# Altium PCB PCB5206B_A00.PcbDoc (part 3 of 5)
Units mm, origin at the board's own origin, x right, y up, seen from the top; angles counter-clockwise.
Board outline 115 x 60 mm, 6 copper layers (Top Layer, GND Layer 2, Signal Layer 3, Signal Layer 4, VCC Layer 5, Bottom Layer), stack 1.555 mm thick; 384 components, 267 nets, 1313 pads, 834 vias.
Unrouted connection lines stored in the file: 10.
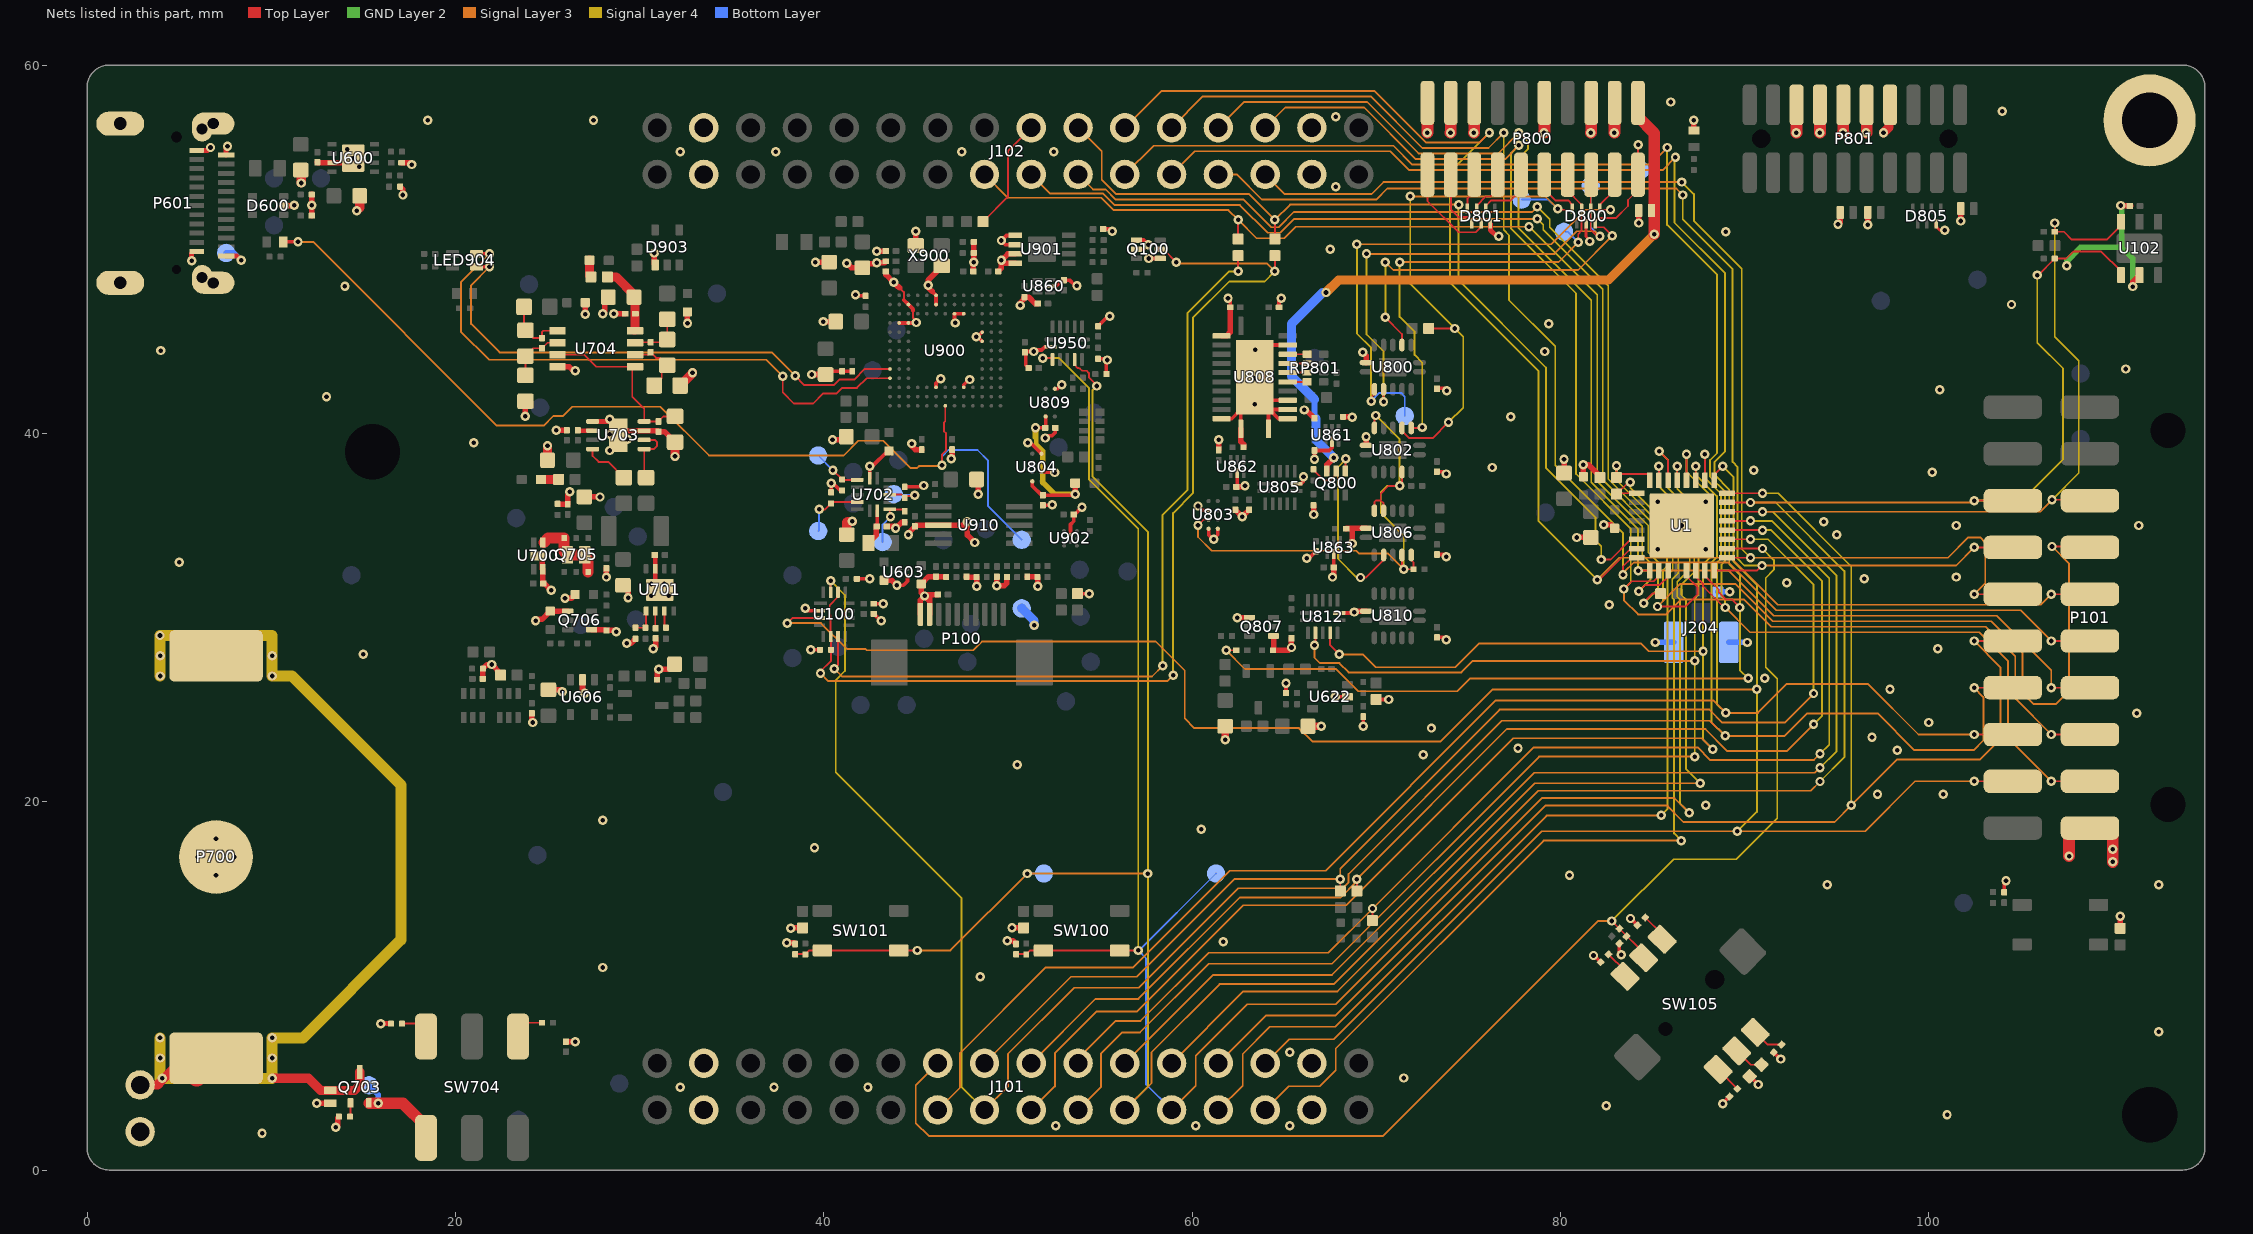
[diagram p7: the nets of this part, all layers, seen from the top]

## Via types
v1: diameter 0.508, hole 0.25, Top Layer to Bottom Layer, tented both sides, 834 vias

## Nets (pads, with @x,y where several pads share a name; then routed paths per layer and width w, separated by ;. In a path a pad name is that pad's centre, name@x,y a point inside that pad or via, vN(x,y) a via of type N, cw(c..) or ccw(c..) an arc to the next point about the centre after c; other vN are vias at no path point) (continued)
DEBUG_TRACECLK: D801.2 P800.12 | length 3.2
  Top Layer w0.1: D801.2@75.95,52.215 75.95,52.35 76.25,52.65 77.3,52.65 77.865,53.215 P800.12@77.865,54.05
DEBUG_TRACED0: D801.3 P800.14 | length 2.5
  Top Layer w0.1: D801.3@75.45,52.215 75.45,52.375 75.95,52.875 76.225,52.875 76.595,53.245 P800.14@76.595,54.05
DEBUG_TRACED1: D801.4 P800.16 | length 2
  Top Layer w0.1: D801.4@74.95,52.215 74.95,52.75 75.325,53.125 P800.16@75.325,54.05
DEBUG_TRACED2: D801.5 P800.18 | length 3.4
  Top Layer w0.1: P800.18@74.055,54.05 74.055,52.17 74.475,51.75 75,51.75 75.2,51.55 D801.5@75.2,51.385
DEBUG_TRACED3: D801.6 P800.20 | length 5.3
  Top Layer w0.1: P800.20@72.785,54.05 72.785,52.615 74.475,50.925 75.4,50.925 75.7,51.225 D801.6@75.7,51.385
DH_#RESET: D800.4 P800.10 R816.1 TPJ811.1 U802.3 | length 32.5
  Top Layer w0.1: U802.3@71.4,40.3 71.4,40.15 71.8,39.75 73.075,39.75 v1(73.925,40.6) ; R816.1@72.85,45.7 v1@74.175,45.7 ; P800.10@79.135,54.05 79.135,53.24 79.725,52.65 80.425,52.65 80.65,52.425 D800.4@80.65,52.215 80.585,52.15 79.85,52.15 v1(79.85,52.193)
  Signal Layer 3 w0.1: v1(71.85,52.875) 79.168,52.875 v1(79.85,52.193)
  Signal Layer 4 w0.1: v1(71.85,52.875) 71.85,48.125 v1(74.275,45.7) 74.725,45.25 74.725,41.4 v1(73.925,40.6)
  Bottom Layer w0.1: TPJ811.1@77.9,52.7 79.343,52.7 v1(79.85,52.193)
DH_TCK_SWCLK: D800.1 P800.4 TPJ818.1 U800.9 | length 30
  Top Layer w0.1: v1(69.725,41.75) 69.725,41.95 69.9,42.125 U800.9@69.9,42.4 ; v1(82.725,52.15) 82.215,52.15 D800.1@82.15,52.215 82.15,52.425 82.945,53.22 P800.4@82.945,54.05
  Signal Layer 3 w0.1: v1(68.95,50.275) 79.5,50.275 81.375,52.15 v1(82.725,52.15)
  Signal Layer 4 w0.1: v1(68.95,50.275) 68.95,45.425 69.725,44.65 v1(69.725,41.75)
  Bottom Layer w0.1: v1(69.725,41.75) 70.175,42.2 71.35,42.2 71.55,42 TPJ818.1@71.55,40.95
DH_TDI: D800.3 P800.8 TPJ820.1 U802.2 | length 25.3
  Top Layer w0.1: U802.2@71.9,40.3 72.475,40.3 v1(72.5,40.325) ; P800.8@80.405,54.05 80.405,53.17 81.15,52.425 D800.3@81.15,52.215 81.15,51 80.975,50.825 v1(80.975,50.375)
  Signal Layer 3 w0.1: v1(71.272,49.3) 79.9,49.3 v1(80.975,50.375)
  Signal Layer 4 w0.1: v1(71.272,49.3) 71.272,46.328 72.082,45.518 72.082,44.268 72.5,43.85 v1(72.5,40.325)
  Bottom Layer w0.1: TPJ820.1@80.2,50.95 80.4,50.95 v1(80.975,50.375)
DH_TDO_SWO: D800.2 P800.6 TPJ812.1 U800.10 | length 28.9
  Top Layer w0.1: v1@70.4,41.825 U800.10@70.4,42.4 ; P800.6@81.675,54.05 81.65,54.025 D800.2@81.65,52.215 81.65,51.05 82,50.7 v1(82.15,50.7)
  Signal Layer 3 w0.1: v1(69.475,49.75) 79.675,49.75 80.9,50.975 81.875,50.975 v1(82.15,50.7)
  Signal Layer 4 w0.1: v1(69.475,49.75) 69.475,45.375 70.4,44.45 v1(70.4,41.725)
  Bottom Layer w0.1: TPJ812.1@81.65,53.45 81.65,51.2 v1(82.15,50.7)
DH_TMS_SWDIO: D800.7 P800.2 TPJ814.1 U800.3 | length 26.5
  Top Layer w0.1: v1(70.5,46.3) 71.4,45.4 U800.3@71.4,44.8 ; v1(82.825,50.725) 82.35,51.2 81.925,51.2 81.9,51.225 D800.7@81.9,51.385 81.9,51.525 82.075,51.7 83.025,51.7 83.675,52.35 83.675,52.675 84.215,53.215 P800.2@84.215,54.05 84.215,55.665 v1(84.225,55.675)
  Signal Layer 3 w0.1: v1(70.5,49.3) 70.925,48.875 80.975,48.875 v1(82.825,50.725)
  Signal Layer 4 w0.1: v1@70.5,46.475 v1(70.5,49.3) v1(70.5,49.3)
  Bottom Layer w0.1: v1(84.225,55.675) 84.225,54.425 TPJ814.1@84.35,54.3
DH_VTREF: D809.1 P800.1 Q800.3 | length 38.3
  Top Layer w0.3: Q800.3@67.325,37.95 67.325,38.3 v1(67.7,38.675)
  Top Layer w0.635: P800.1@84.215,57.95 84.215,57.193 85.1,56.309 v1(85.1,50.825)
  Signal Layer 3 w0.5: v1(67.275,47.65) 67.95,48.325 82.6,48.325 v1(85.1,50.825)
  Bottom Layer w0.35: 66.65,41.85 66.65,40.877 66.725,40.802
  Bottom Layer w0.5: 66.65,41.85 65.4,43.1 65.4,45.95 67.1,47.65 v1(67.275,47.65) ; 66.725,40.802 66.725,39.65 v1(67.7,38.675)
DISP_CS: R300.2 U100.7 | length 44.3
  Top Layer w0.1: v1(40.575,27.225) 40.775,27.425 U100.7@40.775,28.975 ; v1(62.5,48.8) R300.2@62.5,49.65
  Signal Layer 3 w0.1: v1(40.575,27.225) 41,26.8 57.825,26.8 v1(58.4,27.375)
  Signal Layer 4 w0.1: v1(58.4,27.375) 58.4,35.575 59.75,36.925 59.75,46.525 62.025,48.8 v1(62.5,48.8)
DISP_ENABLE: Q100.2 R141.2 R304.2 U100.6 U100.14 | length 57.2
  Top Layer w0.1: v1(39.825,26.975) 39.825,27.075 40.4,27.65 R141.2@40.4,28.25 40.4,28.95 U100.6@40.375,28.975 40.375,30.125 40.325,30.175 40.325,30.675 40.775,31.125 U100.14@40.775,31.375 ; Q100.2@58.275,50 58.45,50 v1(59.15,49.3) ; v1(64.5,48.8) R304.2@64.5,49.65
  Signal Layer 3 w0.1: v1(39.825,26.975) 40.25,26.55 58.65,26.55 v1(58.975,26.875) ; v1(59.15,49.3) 59.225,49.225 64.075,49.225 v1(64.5,48.8)
  Signal Layer 4 w0.1: v1(58.975,26.875) 58.975,35.675 60.05,36.75 60.05,46.275 62.025,48.25 63.95,48.25 v1(64.5,48.8)
DISP_SCLK: J101.15 P101.8 U1.27 U100.15 | length 120.9
  Top Layer w0.1: U100.15@40.375,31.375 v1(40.375,32) ; U1.27@87.35,37.45 v1(87.35,38.225) ; v1(102.47,26.19) P101.8@104.57,26.19
  Signal Layer 3 w0.1: J101.15@48.73,3.262 50,4.532 50,6.3 53.6,9.9 57.1,9.9 62.5,15.3 68.175,15.3 68.5,15.625 68.5,16.075 76.825,24.4 88.125,24.4 v1(88.95,23.575) 92.175,23.575 93.4,24.8 97.225,24.8 99.225,22.8 102.45,22.8 102.975,23.325 102.975,25.685 v1(102.47,26.19)
  Signal Layer 4 w0.1: v1(40.375,32) 41.15,31.225 41.15,27.1 40.65,26.6 40.65,21.6 47.475,14.775 47.475,4.517 J101.15@48.73,3.262 ; v1(87.35,38.225) 87.35,37.75 88.5,36.6 88.5,33.275 88.2,32.975 88.2,24.325 v1(88.95,23.575)
DISP_SI: J101.28 P101.4 U1.25 U100.3 | length 129.2
  Top Layer w0.1: v1(38.025,29.7) 38.3,29.975 U100.3@39.775,29.975 ; U1.25@88.35,37.45 88.35,37.75 v1(88.825,38.225) ; v1(102.47,21.11) P101.4@104.57,21.11
  Signal Layer 3 w0.1: v1(38.025,29.7) 39.85,29.7 41.25,28.3 42.25,28.3 42.325,28.225 48.125,28.225 48.6,28.7 58.025,28.7 59.6,27.125 59.6,24.525 60.125,24 65.8,24 66.525,23.275 73.5,23.275 76.325,26.1 v1(90.675,26.1) ; J101.28@63.97,5.802 65.272,7.104 67.703,7.104 79,18.4 v1(89.6,18.4) 96.55,18.4 99.26,21.11 v1(102.47,21.11)
  Signal Layer 4 w0.1: v1(88.825,38.225) 89.4,37.65 89.4,33.05 90.675,31.775 v1(90.675,26.1) 90.675,19.45 v1@89.613,18.387
EXP_HEADER3: J102.21 P101.3 U1.14 | length 86.5
  Top Layer w0.1: U1.14@87.35,32.55 87.35,32.225 87.75,31.825 87.75,31.688 88.888,30.55 v1(88.95,30.55) ; v1(106.66,21.11) P101.3@108.76,21.11
  Signal Layer 3 w0.1: J102.21@56.35,54.062 57.913,55.625 70.939,55.625 71.964,54.6 84.875,54.6 v1(85.8,55.525) ; v1(88.95,30.55) 90.3,29.2 102.75,29.2 104.3,27.65 104.3,23.47 v1(106.66,21.11)
  Signal Layer 4 w0.1: v1(85.8,55.525) 85.8,51.325 88.513,48.613 88.513,38.938 88.128,38.553 88.128,37.647 88.95,36.825 88.95,33.075 88.75,32.875 88.75,31.15 88.95,30.95 v1(88.95,30.55)
EXP_HEADER5: J102.28 P101.5 U1.10 | length 76.3
  Top Layer w0.1: v1(83.45,31.55) 83.875,31.975 85.075,31.975 85.35,32.25 U1.10@85.35,32.55 ; v1(106.66,23.65) P101.5@108.76,23.65
  Signal Layer 3 w0.1: J102.28@63.97,56.602 65.068,57.7 69.35,57.7 72.15,54.9 77,54.9 v1(77.75,55.65) ; v1(83.45,31.55) 83.45,30.95 84.225,30.175 85.75,30.175 86.55,30.975 89.975,30.975 91.45,29.5 103.1,29.5 104.7,27.9 104.7,25.61 v1(106.66,23.65)
  Signal Layer 4 w0.1: v1(77.75,55.65) 77.325,55.225 77.325,51.125 80.85,47.6 80.85,37.8 83.825,34.825 83.825,31.925 v1(83.45,31.55)
EXP_HEADER6: J101.13 P101.6 U1.26 | length 86.9
  Top Layer w0.1: U1.26@87.85,37.45 v1@87.85,38.85 ; v1(102.47,23.65) P101.6@104.57,23.65
  Signal Layer 3 w0.1: J101.13@46.19,3.262 47.4,4.472 47.4,6.35 52.05,11 56.8,11 62.05,16.25 67.25,16.25 76.5,25.5 88.3,25.5 v1(88.975,24.825) 90.725,24.825 92.3,26.4 96.7,26.4 99.45,23.65 v1(102.47,23.65)
  Signal Layer 4 w0.1: v1(87.85,38.875) 87.85,37.6 88.725,36.725 88.725,33.2 88.5,32.975 88.5,25.3 v1(88.975,24.825)
EXP_HEADER7: J102.26 P101.7 U1.9 | length 73.8
  Top Layer w0.1: v1(84.225,32.55) U1.9@84.85,32.55 ; v1(106.66,26.19) P101.7@108.76,26.19
  Signal Layer 3 w0.1: J102.26@61.43,56.602 62.828,58 69.5,58 72.3,55.2 76.625,55.2 v1(77.75,56.325) ; v1(84.225,32.55) 89.15,32.55 91.6,30.1 103.7,30.1 106.66,27.14 v1(106.66,26.19)
  Signal Layer 4 w0.1: v1(77.75,56.325) 78.25,55.825 78.25,55.45 77.725,54.925 77.725,51.175 81.675,47.225 81.675,37.35 84.225,34.8 v1(84.225,32.55)
EXP_HEADER9: J102.24 P101.9 U1.8 | length 75.8
  Top Layer w0.1: v1(83.4,32.325) 83.4,32.775 83.875,33.25 U1.8@84.15,33.25 ; v1(106.66,28.73) P101.9@108.76,28.73
  Signal Layer 3 w0.1: J102.24@58.89,56.602 60.588,58.3 69.7,58.3 72.5,55.5 76.1,55.5 v1(76.925,56.325) ; v1@83.45,32.325 83.45,32.45 84,33 89.125,33 91.725,30.4 104.99,30.4 v1(106.66,28.73)
  Signal Layer 4 w0.1: v1(76.925,56.325) 76.925,51.05 77.213,50.762 77.213,47.237 79.725,44.725 79.725,38.275 83.4,34.6 v1(83.4,32.325)
EXP_HEADER10: J101.26 P101.10 U1.24 | length 79.9
  Top Layer w0.1: U1.24@89.05,36.75 v1@90.95,36.75 ; v1(102.47,28.73) P101.10@104.57,28.73
  Signal Layer 3 w0.1: J101.26@61.43,5.802 64.028,8.4 67.8,8.4 79.2,19.8 85.775,19.8 86.675,18.9 94.9,18.9 v1(95.8,19.8) 98.3,22.3 102.8,22.3 103.9,23.4 103.9,27.3 v1(102.47,28.73)
  Signal Layer 4 w0.1: v1(90.975,36.75) 91.825,36.75 95.8,32.775 v1(95.8,19.8)
EXP_HEADER11: J102.22 P101.11 U1.7 | length 81.9
  Top Layer w0.1: v1(82,32.05) 82.125,32.05 83.825,33.75 U1.7@84.15,33.75 ; v1(106.66,31.27) P101.11@108.76,31.27
  Signal Layer 3 w0.1: J102.22@56.35,56.602 58.348,58.6 69.9,58.6 72.7,55.8 75.625,55.8 v1(76.15,56.325) ; v1(82,32.05) 83.2,33.25 89.25,33.25 91.8,30.7 106.09,30.7 v1(106.66,31.27)
  Signal Layer 4 w0.1: v1(76.15,56.325) 74,54.175 74,48.2 78.819,43.381 78.819,35.231 v1(82,32.05)
EXP_HEADER12: J102.27 P101.12 U1.17 | length 65
  Top Layer w0.1: U1.17@89.05,33.25 v1(90.325,33.25) ; v1(102.47,31.27) P101.12@104.57,31.27
  Signal Layer 3 w0.1: J102.27@63.97,54.062 65.032,53 69.746,53 70.396,53.65 v1(86.6,53.65) ; v1(90.325,33.25) 101.05,33.25 102.15,34.35 102.8,34.35 103.075,34.075 103.075,31.875 v1(102.47,31.27)
  Signal Layer 4 w0.1: v1(86.6,53.65) 86.6,53.644 87.25,52.994 87.25,51.55 89.85,48.95 89.85,33.725 v1(90.325,33.25)
EXP_HEADER13: J102.19 P101.13 U1.13 | length 92.9
  Top Layer w0.1: v1(85.275,30.6) 86.775,30.6 87.45,31.275 87.45,31.65 86.85,32.25 U1.13@86.85,32.55 ; v1(106.7,33.86) P101.13@108.8,33.86
  Signal Layer 3 w0.1: J102.19@53.81,54.062 54.622,53.25 55.3,53.25 55.85,52.7 62.8,52.7 64.3,51.2 64.7,51.2 65.525,52.025 78.475,52.025 v1(78.75,52.3) ; v1(85.275,30.6) 86.5,31.825 89.5,31.825 91.525,29.8 103.4,29.8 105.1,28.1 105.1,25.9 105.7,25.3 106.9,25.3 107.625,26.025 107.625,32.935 v1(106.7,33.86)
  Signal Layer 4 w0.1: v1(78.75,52.3) 79.425,51.625 79.425,51.2 82.6,48.025 82.6,37.525 85.8,34.325 85.8,32.8 85.575,32.575 85.575,30.9 v1(85.275,30.6)
EXP_HEADER14: J102.25 P101.14 U1.16 | length 65.4
  Top Layer w0.1: U1.16@88.35,32.55 90.675,32.55 v1(90.95,32.825) ; v1(102.47,33.81) P101.14@104.57,33.81
  Signal Layer 3 w0.1: J102.25@61.43,54.062 62.438,54.062 63.8,52.7 70,52.7 70.6,53.3 86.3,53.3 v1(86.65,52.95) ; v1(90.95,32.825) 101.485,32.825 v1(102.47,33.81)
  Signal Layer 4 w0.1: v1(86.65,52.95) 86.65,51.625 89.35,48.925 89.35,38.45 89.625,38.175 89.625,33.2 90,32.825 v1(90.95,32.825)
EXP_HEADER15: J101.22 P101.15 R109.2 U1.22 U102.6 | length 101.6
  Top Layer w0.1: U1.22@89.05,35.75 v1@90.95,35.75 ; v1(106.7,36.4) P101.15@108.8,36.4 ; v1(106.85,51.425) R109.2@106.85,50.95 107.35,50.95 107.775,50.525 109.675,50.525 110.45,51.3 U102.6@110.45,51.5
  Signal Layer 3 w0.1: J101.22@56.35,5.802 61.148,10.6 67.6,10.6 78.575,21.575 93.825,21.575 v1(94.1,21.85) ; v1(90.975,35.75) 106.05,35.75 v1(106.7,36.4)
  Signal Layer 4 w0.1: v1(90.975,35.75) 91.525,35.75 95,32.275 95,22.75 v1(94.1,21.85) ; v1(106.7,36.4) 108.15,37.85 108.15,43.95 106.85,45.25 v1(106.85,51.425)
EXP_HEADER16: J101.24 P101.16 R108.2 U1.23 U102.1 | length 97.8
  Top Layer w0.1: U1.23@89.05,36.25 v1(90.325,36.25) ; v1(102.47,36.35) P101.16@104.57,36.35 ; v1(105.9,48.6) 105.95,48.6 R108.2@106.85,49.5 107.475,49.5 107.85,49.875 109.375,49.875 110.45,48.8 U102.1@110.45,48.6
  Signal Layer 3 w0.1: J101.24@58.89,5.802 62.788,9.7 67.9,9.7 78.8,20.6 93.6,20.6 v1(94.1,21.1) ; v1(90.325,36.25) 102.37,36.25 v1(102.47,36.35)
  Signal Layer 4 w0.1: v1(90.325,36.25) 91.7,36.25 95.425,32.525 95.425,22.425 v1(94.1,21.1) ; v1(102.47,36.35) 105.05,36.35 107.3,38.6 107.3,43.525 105.9,44.925 v1(105.9,48.6)
GND: C1.2 C2.2 C3.2 C4.2 C8.2 C102.2 C103.2 C104.2 C106.2 C110.2 C143.2 C144.2 C600.2 C602.2 C607.2 C608.2 C609.2 C610.2 C611.2 C621.2 C625.2 C632.2 C635.2 C638.2 C641.2 C652.2 C653.2 C655.2 C660.2 C700.2 C701.2 C702.2 C703.2 C705.2 C706.2 C707.2 C708.2 C709.2 C714.2 C720.2 C724.2 C728.2 C729.2 C730.2 C731.2 C747.2 C761.2 C762.2 C800.2 C803.2 C804.2 C805.2 C806.2 C807.2 C808.2 C809.2 C810.2 C827.2 C828.2 C860.2 C861.2 C862.2 C863.2 C864.2 C865.2 C866.2 C867.2 C900.2 C901.2 C902.2 C903.2 C904.2 C905.2 C906.2 C907.2 C908.2 C909.2 C910.2 C911.2 C914.2 C919.2 C921.2 C922.2 C924.2 C925.2 C926.2 C927.2 C950.2 C951.2 D600.2 D703.2 D800.6 D801.7 D805.7 D806.2 D807.2 D808.2 D809.2 D903.1 J101.3 J101.4 J101.29 J101.30 J102.3 J102.4 J102.29 J102.30 J204.2 J204.3 LED900.2 M1.1 P100.1 P100.2 P101.1 P601.25@1.8,56.82 P601.26@1.8,48.18 P601.27@6.25,56.525 P601.27@6.85,56.82 P601.28@6.25,48.475 P601.28@6.85,48.18 P601.A1 P601.A12 P601.B1 P601.B12 P700.2 P800.3 P800.5 P800.9 P800.15 P800.17 P800.19 P801.7 P801.9 P801.11 P801.13 P801.15 Q100.1 Q100.4 Q100.5 Q706.1 Q706.4 Q807.1 Q807.4 R6.1 R7.1 R104.2 R105.2 R113.1 R124.1 R125.1 R126.1 R127.1 R140.1 R141.1 R146.1 R220.1 R602.1 R620.1 R621.1 R623.1 R628.2 R631.1 R634.1 R637.1 R640.1 R674.2 R688.2 R691.2 R703.1 R705.1 R706.1 R707.1 R708.1 R718.1 R754.1 R760.1 R763.1 R767.1 R771.1 R792.1 R794.2 R814.1 R839.1 R850.1 R851.1 R852.1 R853.1 R930.2 R931.2 R950.2 R981.2 ST701.1 TPJ614.1 TPJ913.1 U1.33 U100.2 U102.2 U600.3 U600.9 U603.A1 U606.2 U622.2 U700.2 U700.5 U701.3 U701.9 U702.7 U703.3 U703.5 U703.9 U704.4 U800.7 U802.7 U803.B1 U803.D1 U803.D2 U804.B1 U804.D1 U805.7 U806.7 U808.2 U808.11 U808.12 U808.13 U808.14 U808.15 U808.16 U808.22 U808.25 U809.D1 U810.7 U812.7 U860.2 U861.2 U862.2 U863.2 U900.C5 U900.C8 U900.H3 U900.J3 U900.K11 U900.K12 U900.L5 U900.L6 U900.M8 U900.M11 U900.N8 U901.1 U901.2 U901.3 U901.4 U902.B2 U910.3 U950.7 X900.2 X900.4 | length 206.5
  Top Layer w0.1: 44.125,47.9 44.35,47.675 44.35,47.25 ; 44.85,46.674 44.85,46.275 v1@45.025,46.1
  Top Layer w0.15: D800.6@81.4,51.385 81.4,50.7 81.6,50.5 v1(81.6,50.425) ; D805.7@100.4,51.385 100.4,51.25 100.6,51.05 v1@101.05,51.05
  Top Layer w0.2: v1(39,30.5) 39.125,30.375 U100.2@39.775,30.375 ; v1(39.3,28.25) R141.1@39.8,28.25 ; C907.2@40.1,43.2 40.275,43.375 C924.2@41,43.375 C925.2@41.55,43.375 ; R705.1@40.4,36.8 v1(40.4,37.3) 40.5,37.3 40.9,36.9 R706.1@41,36.9 ; v1@41.725,47.5 41.75,47.475 R763.1@42.275,47.475 ; R140.1@41.8,32.1 v1(42.5,32.1) ; U702.7@42.5,37.56 v1(42.5,38.225) 42.65,38.225 43.475,39.05 C901.2@43.55,39.05 ; C104.2@42.725,30.2 43.1,29.825 v1(43.125,29.825) ; C144.2@42.725,30.75 v1(43.225,30.75) ; v1(43.975,31.75) 44.325,31.75 44.55,31.975 U603.A1@44.55,32.25 ; U900.K12@44.1,46 U900.K11@44.6,46 45,46 v1(45.025,46.025) v1@45.025,46.1 ; 44.35,47.25 U900.M11@44.6,47 44.85,46.75 44.85,46.674 ; R707.1@44.4,37.1 45.35,37.1 v1(45.425,37.175) ; 45.885,47.71 46.095,47.5 U900.N8@46.1,47.5 U900.M8@46.1,47 ; U900.C8@46.1,42.5 46.1,42.725 v1(46.35,42.975) ; v1(47.15,46) 47.1,46.05 U900.L6@47.1,46.5 U900.L5@47.6,46.5 ; U900.C5@47.6,42.5 47.6,42.65 v1@47.875,42.925 ; v1@48.224,45.25 v1(48.275,45.25) 48.3,45.25 v1@48.325,45.275 ; U900.H3@48.6,45 v1@48.325,45.275 ; U900.J3@48.6,45.5 48.375,45.275 v1@48.325,45.275 ; U901.2@50.4,50.25 49.875,50.25 v1(49.65,50.475) 49.925,50.75 U901.1@50.4,50.75 ; C911.2@50.925,44.375 C911.2@50.95,44.375 ; C911.2@50.925,44.4 C911.2@50.95,44.375 ; C909.2@51.125,43.55 50.975,43.7 50.975,44.35 C911.2@50.95,44.375 ; v1@51.225,39.45 51.275,39.45 U804.D1@51.825,38.9 ; v1@51.35,44.5 v1@51.35,44.45 ; U804.B1@51.825,37.9 52.525,37.9 v1(52.55,37.875) ; C804.2@51.9,36.1 52.375,36.1 v1(52.4,36.125) ; v1(52.025,39.75) 52.15,39.875 52.4,39.875 52.575,40.05 C810.2@52.575,40.3 ; U860.2@52.3,48 52.625,48 52.95,48.325 C862.2@53.05,48.325 53.35,48.325 53.6,48.075 v1@53.6,47.975 ; U950.7@52.34,44.7 52,44.7 51.83,44.53 51.48,44.53 v1(51.4,44.45) ; U809.D1@52.55,42.425 52.7,42.425 v1(52.925,42.65) ; U902.B2@53.4,34.5 53.4,35.05 53.575,35.225 C914.2@53.575,35.55 ; C914.2@53.575,35.6 C914.2@53.575,35.55 ; R146.1@53.775,31.3 v1(54.425,31.3) ; v1(54.025,36) C914.2@53.575,35.55 ; R950.2@54.9,44.05 v1@55.4,44.05 ; C950.2@54.9,45.825 55.4,46.325 v1@55.4,46.362 ; C951.2@55.175,51.1 55.55,51.1 v1(55.675,50.975) ; R981.2@55.35,43.225 55.35,43.937 v1(55.4,43.987) ; Q100.5@56.975,50 57.375,50 v1(57.625,50.25) 57.375,50.5 Q100.4@56.975,50.5 ; v1(57.65,49.5) Q100.1@58.275,49.5 ; v1(60.325,36.058) 60.558,35.825 U803.B1@60.9,35.825 ; U803.D1@60.9,34.825 60.9,34.5 61.15,34.25 61.4,34.5 U803.D2@61.4,34.825 ; U808.11@61.605,40.8 62.15,40.8 U808.25@62.65,41.3 ; v1(61.95,47.35) 62.075,47.225 C808.2@62.075,46.85 ; C860.2@62.4,37.1 62.45,37.15 U862.2@62.45,37.85 ; U808.12@62.65,40.255 U808.25@62.65,41.3 ; v1(63.425,44.55) 63.675,44.8 U808.22@65.195,44.8 ; U808.13@64.15,40.255 U808.25@64.15,41.3 ; C806.2@64.725,46.85 64.725,47.225 v1(64.85,47.35) ; R688.2@65.1,25.9 v1(65.1,26.425) ; U808.14@65.195,40.8 64.7,40.8 U808.25@64.2,41.3 ; U808.15@65.195,41.3 U808.25@64.2,41.3 ; U808.16@65.195,41.8 63.625,41.8 v1(63.4,41.575) ; U805.7@65.66,37.27 65.92,37.27 66.025,37.375 66.025,37.625 v1(66.05,37.65) ; v1(66.225,33.225) 66.35,33.225 C867.2@66.725,33.6 ; v1(66.65,38.6) C864.2@66.65,39.075 67.45,39.075 67.6,39.225 U861.2@67.6,39.55 ; C866.2@67.7,32.725 U863.2@67.7,33.45 ; v1(67.775,25.7) U622.2@68.45,25.7 ; U812.7@67.985,30.25 68.75,30.25 v1(68.8,30.3) ; v1(69.3,24.1) C653.2@69.3,24.625 ; R691.2@70,25.55 v1(70.675,25.55) ; C827.2@73.3,28.925 73.675,28.925 v1(73.8,28.8) ; C809.2@73.3,33.425 73.675,33.425 v1(73.8,33.3) ; C805.2@73.3,37.925 73.675,37.925 v1(73.8,37.8) ; C803.2@73.325,42.45 73.7,42.45 v1(73.825,42.325) ; v1(81.8,11.65) 81.826,11.65 R124.1@82.188,11.288 ; C106.2@83.206,12.306 83.206,11.794 v1(83.3,11.7) ; v1(83.807,13.657) 83.833,13.657 R127.1@84.195,13.295 ; v1(88.826,3.6) 88.826,3.626 R125.1@89.188,3.988 ; R113.1@90.282,5.082 90.308,5.082 v1(90.745,4.645) ; R126.1@91.588,6.388 91.95,6.026 v1(91.976,6.026) ; C8.2@104.1,15.075 104.1,15.6 v1(104.2,15.7) ; C911.2@50.95,44.375 50.993,44.375 51.068,44.45 v1@51.35,44.45 ; v1@51.35,44.45 51.35,44.399 v1(51.4,44.45) ; v1@51.35,44.45 v1(51.4,44.45) ; U808.25@62.65,41.3 62.925,41.575 v1(63.4,41.575) ; v1(63.4,41.575) 63.675,41.3 U808.25@64.15,41.3 ; U808.25@64.15,41.3 U808.25@64.2,41.3
  Top Layer w0.25: U703.5@27.45,40.65 v1@28.25,40.65 ; C702.2@30.825,33.4 30.85,33.375 U701.3@30.85,32.65 30.85,31.75 U701.9@31.1,31.5
  Top Layer w0.27: v1(5.675,49.375) 5.675,49.775 5.775,49.875 P601.B1@5.95,49.875 ; P601.B12@5.95,55.375 6.55,55.375 v1(6.7,55.525) ; P601.A12@7.55,49.625 8.15,49.625 v1(8.375,49.4) ; P601.A1@7.55,55.125 7.55,55.5 7.625,55.575 v1(7.625,55.6) ; v1(15.95,7.95) R794.2@16.5,7.95 ; D801.7@76.2,51.385 76.2,51.05 76.55,50.7 v1(76.65,50.7)
  Top Layer w0.3: D600.2@10.675,52.375 11.225,52.375 v1(11.25,52.4) ; R621.1@12.2,51.825 12.2,51.9 v1(12.2,52.4) 12.2,52.9 R620.1@12.2,52.975 ; v1(12.475,3.625) D703.2@13.2,3.625 ; C600.2@12.5,54.725 12.525,54.7 U600.3@13.3,54.7 U600.9@14.2,54.7 ; v1(13.501,2.325) 13.6,2.424 13.6,2.825 R792.1@13.675,2.9 ; R602.1@17,53.4 17.15,53.25 v1(17.15,52.95) ; C602.2@17.075,54.7 17.525,54.7 v1(17.625,54.6) ; C610.2@21.475,26.675 21.475,27.2 R623.1@21.5,27.225 21.725,27.45 v1(21.975,27.45) 22.45,26.975 R628.2@22.45,26.875 ; v1(23.8,40.925) R767.1@23.8,41.75 ; C621.2@24.15,24.8 24.15,24.35 v1(24.2,24.3) ; v1(24.352,29.826) 24.425,29.9 24.7,29.9 C709.2@25.15,30.35 Q706.4@26.1,30.35 ; U700.5@24.5,33.35 24.725,33.35 24.725,32.65 U700.2@24.75,32.625 24.75,31.875 C708.2@24.775,31.85 24.825,31.85 v1(25.2,31.475) ; C660.2@25.05,26.075 25.7,26.075 v1(25.8,25.975) ; v1(25.475,40.175) C728.2@26.05,40.175 ; U704.4@25.545,43.625 26.175,43.625 26.4,43.4 v1(26.5,43.4) ; R760.1@25.55,36.175 25.575,36.15 C701.2@26.1,36.15 26.1,36.65 26.2,36.75 v1(26.2,36.825) ; v1(25.95,31.05) 26.3,31.05 C747.2@26.5,31.25 ; C706.2@26,6.975 v1(26.5,6.975) ; U606.2@26.9,26.625 26.9,26.025 v1(27.025,25.9) ; C700.2@27,36.55 v1(27.85,36.55) ; v1(27.05,46.475) C720.2@27.05,47.1 ; Q706.1@27.4,29.35 28.15,29.35 R754.1@28.2,29.3 28.625,29.3 28.7,29.225 v1(28.725,29.225) ; v1(28,46.5) 28.1,46.6 28.1,47.2 C731.2@28.3,47.4 ; v1(28.2,32.2) 28.2,32.225 C762.2@28.2,32.675 ; v1@28.25,40.65 v1(28.375,40.775) ; v1(28.6,46.5) C730.2@29.225,46.5 ; U703.9@28.85,39.625 28.9,39.675 U703.9@29.075,39.675 ; C761.2@29.1,31.75 29.375,31.475 v1(29.375,31.075) ; v1(29.3,28.6) 29.525,28.6 R703.1@29.775,28.85 ; v1(29.325,39.675) U703.9@29.075,39.675 ; v1(30.75,28.3) 30.875,28.425 C705.2@30.875,28.875 ; v1(30.8,49.8) 30.8,49.2 D903.1@30.85,49.15 ; R674.2@30.95,26.625 30.95,27.1 v1(31.05,27.2) 31.625,27.2 C625.2@31.9,27.475 ; R718.1@31.925,39.525 31.35,40.1 C729.2@31.025,40.1 30.975,40.15 U703.3@30.25,40.15 29.1,40.15 U703.9@28.85,39.9 U703.9@29.075,39.675 ; v1(32.6,45.975) C724.2@32.6,46.6 ; v1(38,12.35) 38.375,12.35 C103.2@38.45,12.275 ; v1(38.2,13.125) 38.225,13.15 R105.2@38.85,13.15 ; v1(39.35,43.2) C907.2@40.1,43.2 ; v1(39.55,49.3) C919.2@40.3,49.3 ; v1(39.975,46.075) C900.2@40.65,46.075 ; v1(40.475,39.65) 41.05,39.65 C902.2@41.225,39.825 ; v1(41.25,49.25) 41.5,49 C903.2@42.1,49 42.325,49.225 42.825,49.225 v1(42.875,49.275) 43.3,49.275 C905.2@43.375,49.35 ; v1(42.875,49.9) C906.2@43.375,49.9 ; C609.2@43.275,32.025 43.7,32.025 v1(43.975,31.75) ; C904.2@43.375,48.8 43.375,48.625 v1(43.8,48.2) 44,48 44.025,48 44.125,47.9 ; C707.2@43.425,34.95 43.8,34.95 v1(43.9,34.85) ; v1@43.925,34.85 v1(43.9,34.85) ; R708.1@44.4,35.175 44.225,35.175 v1(43.9,34.85) ; v1(44.6,34.5) 44.6,34.6 C922.2@44.95,34.95 45.025,35.025 U910.3@46.225,35.025 47.625,35.025 v1(47.8,35.2) ; v1(44.775,39.45) 44.775,39.325 44.975,39.125 C927.2@45.325,39.125 ; X900.4@45,50.2 v1(45,50.975) ; P100.1@45.25,30.175 45.25,30.95 v1(45.475,31.175) ; v1@45.675,48.05 45.675,48.325 46.4,49.051 X900.2@46.4,49.1 ; v1(45.675,48.05) 45.675,47.92 45.885,47.71 ; P100.2@45.75,30.175 45.75,30.9 ; C143.2@46.2,31.25 45.75,31.25 ; R637.1@46.65,32.2 46.625,32.225 C638.2@46.1,32.225 45.7,32.225 C608.2@45.3,31.825 45.3,31.35 v1(45.475,31.175) ; v1@46.975,38.625 C926.2@46.975,39.125 ; C641.2@47.75,32.225 47.775,32.2 R640.1@48.3,32.2 v1(48.3,31.7) ; v1@47.825,35.225 v1(47.8,35.2) ; C910.2@48.125,48.8 48.125,49.275 v1(48.15,49.3) R930.2@48.15,49.8 R931.2@48.15,50.4 ; v1(48.2,34.075) 47.8,34.475 v1(47.8,35.2) ; C921.2@48.3,37.5 48.4,37.4 v1(48.4,36.7) ; C635.2@49.4,32.225 v1(49.4,31.725) 49.8,31.725 49.95,31.875 R634.1@49.95,32.2 ; C908.2@49.475,48.8 49.65,48.975 v1(49.65,49.4) ; v1(49.975,12.45) 50.275,12.45 C102.2@50.45,12.275 ; v1(50.225,13.15) R104.2@50.85,13.15 ; U901.4@50.4,49.25 49.8,49.25 v1(49.65,49.4) ; U901.3@50.4,49.75 50,49.75 v1(49.65,49.4) ; v1(50.675,46.95) 50.675,47.095 50.868,47.288 50.868,47.368 R850.1@50.9,47.4 51.133,47.4 51.483,47.05 C863.2@51.625,47.05 ; C632.2@51.05,32.225 51.575,32.225 R631.1@51.6,32.2 51.625,32.175 v1(51.625,31.7) ; C861.2@61.45,39.1 v1(61.45,39.65) ; U808.2@61.605,45.3 61.875,45.3 62.075,45.5 C808.2@62.075,46.85 ; C807.2@62.35,35.85 v1(62.725,35.475) C800.2@63.1,35.85 ; C860.2@62.4,37.1 62.825,37.1 v1(62.875,37.15) ; v1(62.45,30) Q807.4@63.125,30 ; U808.12@62.65,40.255 62.65,39.55 62.8,39.4 R852.1@62.8,39.25 ; Q807.1@64.425,29 64.425,28.25 R839.1@64.4,28.225 65.25,28.225 v1(65.4,28.375) C828.2@65.4,28.875 ; v1(66.1,41.275) 66.2,41.275 C865.2@66.65,40.825 ; R814.1@66.6,36.1 66.6,35.725 66.65,35.675 v1@66.65,35.6 ; v1(67.625,32.2) 67.7,32.275 C866.2@67.7,32.725 ; R851.1@68.2,40.9 68.675,40.9 v1(68.7,40.875) ; R853.1@68.375,34.825 68.4,34.85 68.678,34.85 ; v1(68.7,34.025) 68.7,34.822 68.675,34.847 68.678,34.85 ; v1(68.8,30.3) 68.85,30.35 U810.7@69.45,30.35 ; v1(69.275,44.4) 69.45,44.225 U800.7@69.45,43.85 ; U806.7@69.45,34.85 68.678,34.85 ; U802.7@69.45,39.35 v1(69.45,39.825) ; C3.2@80.2,37.85 v1(80.2,38.6) ; v1(80.9,34.35) C1.2@81.65,34.35 ; C4.2@81.25,37.65 v1(81.25,38.3) 81.525,38.3 82.15,37.675 R6.1@82.15,37.6 ; v1(82.35,35.05) 82.75,35.05 C2.2@82.95,34.85 ; v1(84.25,51.425) D809.2@84.25,52.1 ; LED900.2@87.25,56.45 v1(87.25,57) ; v1(95.075,51.35) 95.2,51.475 D806.2@95.2,52 ; v1(96.7,51.325) D807.2@96.7,52 ; v1(101.75,51.534) D808.2@101.75,52.209 ; R7.1@110.4,13.125 v1(110.4,13.775) ; v1@110.475,52.375 C110.2@110.975,52.375 ; v1(111.075,47.975) 111.075,48.225 U102.2@111.45,48.6 ; v1(45.475,31.175) 45.55,31.25 45.75,31.25 ; v1(45.475,31.175) 45.75,30.9 ; 45.75,30.9 45.75,31.25
  Top Layer w0.4: v1@61.8,23.425 C655.2@61.8,24.1 ; C652.2@66.3,24.1 v1@66.975,24.1
  Top Layer w0.5: C611.2@11.6,54.3 11.5,54.3 11.625,54.175 v1(11.625,53.6) ; v1(14.65,52.1) 14.8,52.25 C607.2@14.8,52.9 ; C714.2@25,38.55 v1(25,39.325) ; v1(31.925,38.75) R718.1@31.925,39.525 ; R771.1@32.2,42.6 32.875,43.275 v1(32.875,43.3) ; C703.2@41.25,34.5 41.25,35.175 41.3,35.225 v1(41.55,35.225) ; v1(97.55,56.325) 97.85,56.625 97.85,57.786 P801.7@97.905,57.841
  Top Layer w0.635: v1(72.765,56.325) 72.785,56.345 P800.19@72.785,57.95 ; v1(74.035,56.325) 74.055,56.345 P800.17@74.055,57.95 ; v1(75.305,56.325) 75.325,56.345 P800.15@75.325,57.95 ; v1(79.115,56.325) 79.135,56.345 P800.9@79.135,57.95 ; v1(81.655,56.325) 81.675,56.345 P800.5@81.675,57.95 ; v1(82.925,56.325) 82.945,56.345 P800.3@82.945,57.95 ; v1(92.81,56.325) 92.835,56.325 92.825,56.335 P801.15@92.825,57.841 ; v1(94.08,56.325) 94.105,56.325 94.095,56.335 P801.13@94.095,57.841 ; v1(95.35,56.325) 95.375,56.325 95.365,56.335 P801.11@95.365,57.841 ; v1@96.635,56.335 P801.9@96.635,57.841 ; v1(107.625,17.05) 107.625,18.25 107.945,18.57 P101.1@108.76,18.57 109.705,18.57 110,18.275 v1(110,17.425) v1(110,16.75) v1@110,16.725
  GND Layer 2 w0.3: v1(107.505,49.102) 107.5,49.108 107.5,49.35 108.25,50.1 110.475,50.1 ; v1@110.475,52.375 110.475,50.1 ; v1(111.075,47.975) 111.075,49.5 110.475,50.1
  Signal Layer 4 w0.3: v1(24.352,29.826) v1@24.375,29.85
  Bottom Layer w0.3: TPJ614.1@7.55,49.8 7.975,49.8 v1(8.375,49.4) ; v1(85.15,28.65) J204.3@86.15,28.65 ; R220.1@88.55,31.4 v1(89.2,31.4) ; J204.2@89.15,28.65 v1(90.15,28.65)
  Bottom Layer w0.5: TPJ913.1@50.751,30.501 51.425,29.828 v1(51.425,29.575)
  other v1: 9.5,2 52.6,2.4 60.2,2.4 65.3,2.4 101,3 82.5,3.5 32.2,4.5 37.3,4.5 42.4,4.5 71.5,5 65.3,6.4 112.5,7.5 48.5,10.5 28,11 61.7,12.4 94.5,15.5 112.5,15.5 7,16 80.5,16 6,17 8,17 39.5,17.5 7,18 60.5,18.5 28,19 87.9,19.8 97.225,20.4 100.8,20.4 50.5,22 72.55,22.55 98.3,22.8 77.7,22.9 61.8,23.375 96.925,23.5 73,24 67.025,24.1 100,24.3 111.3,24.8 97.9,26.1 91.1,26.7 15,28 100.5,28.3 82.65,30.7 30.625,31.175 31.575,31.175 30.625,31.825 31.35,31.825 92.3,31.9 96.5,32.1 101.5,32.2 5,33 85.3,33.7 87.9,33.7 61.175,34.25 95,34.5 86.6,35 101.5,35 111.4,35 94.3,35.2 66.6,35.6 85.3,36.3 87.9,36.3 100.2,37.9 90.5,38 76.3,38.15 46.925,38.625 28.375,39.075 21,39.5 51.075,39.5 28.375,39.95 77.3,40.9 13,42 100.6,42.375 47.925,42.925 63.4,43 110.7,43.5 79.15,44.45 4,44.5 79.375,45.95 55.525,46.362 104.5,47 41.725,47.525 14,48 53.75,48.025 67.5,50 88.975,50.95 100.875,51.025 110.425,52.375 67.8,53.4 14.775,54.475 14.45,54.95 32.2,55.3 37.4,55.3 47.5,55.3 52.5,55.3 14.125,55.425 96.6,56.325 18.5,57 27.5,57 67.8,57.2 104,57.5 86,58
JS_A: R125.2 SW105.1 | length 1.5
  Top Layer w0.1: SW105.1@88.57,5.464 89.612,4.423 R125.2@89.612,4.412
JS_B: R126.2 SW105.3 | length 1.7
  Top Layer w0.1: SW105.3@90.586,7.48 91.253,6.812 R126.2@92.012,6.812
JS_C: R127.2 SW105.6 | length 1.6
  Top Layer w0.1: R127.2@84.612,13.712 85.53,12.795 SW105.6@85.53,12.536
JS_CEN: R113.2 SW105.2 | length 1.7
  Top Layer w0.1: SW105.2@89.578,6.472 90.332,5.718 R113.2@90.918,5.718
JS_D: R124.2 SW105.4 | length 1.6
  Top Layer w0.1: R124.2@82.612,11.712 83.514,10.81 SW105.4@83.514,10.52
LED_JLINK: LED901.2 TPJ912.1 U900.A7 | length 54
  Top Layer w0.1: v1(46.425,38.275) 46.425,38.864 46.643,39.082 46.643,40.007 46.525,40.125 46.525,40.575 46.6,40.65 U900.A7@46.6,41.5
  Top Layer w0.2: LED901.2@10.65,50.4 v1@11.25,50.4
  Signal Layer 3 w0.1: v1(11.45,50.4) 12.275,50.4 22.25,40.425 24.8,40.425 25.325,40.95 25.85,40.95 26.35,41.45 31.125,41.45 33.775,38.8 41.075,38.8 41.875,39.6 43.225,39.6 44.7,38.125 45.075,38.125 45.175,38.225 46.375,38.225 v1(46.425,38.275)
  Bottom Layer w0.1: v1(46.425,38.275) 46.425,38.75 46.775,39.1 48.35,39.1 48.925,38.525 48.925,36.051 TPJ912.1@50.751,34.225
LED_STATUS_G: LED904.3 U900.D13 | length 31.6
  Top Layer w0.1: v1(37.775,43.1) 37.775,42.225 38.375,41.625 39.425,41.625 39.975,42.175 40.7,42.175 41,42.475 41.8,42.475 42.325,43 U900.D13@43.6,43
  Top Layer w0.2: LED904.3@21.15,49.75 v1(21.85,49.75)
  Signal Layer 3 w0.1: v1(21.85,49.75) 20.3,48.2 20.3,45.525 21.825,44 36.875,44 v1(37.775,43.1)
LED_STATUS_R: LED904.4 U900.E13 | length 28.7
  Top Layer w0.1: v1(38.45,43.125) 38.95,42.625 40.55,42.625 40.85,42.925 41.65,42.925 42.225,43.5 U900.E13@43.6,43.5
  Top Layer w0.2: LED904.4@21.15,49.05 v1(21.85,49.05)
  Signal Layer 3 w0.1: v1(21.85,49.05) 20.85,48.05 20.85,45.95 22.4,44.4 37.175,44.4 v1(38.45,43.125)
MCU_P0.0: J101.27 R5.2 U1.1 | length 52.3
  Top Layer w0.1: R5.2@83.05,36.7 R5.2@83.1,36.75 ; v1(83.8,37.35) 83.7,37.35 R5.2@83.1,36.75 ; U1.1@84.15,36.75 R5.2@83.1,36.75
  Signal Layer 3 w0.1: J101.27@63.97,3.262 65.258,4.55 66.925,4.55 67.8,5.425 67.8,6.6 79.089,17.889 v1(86.564,17.889)
  Signal Layer 4 w0.1: v1(83.8,37.35) 83.8,37.05 86.4,34.45 86.4,32.4 86.075,32.075 86.075,31.075 86.175,30.975 86.175,18.277 v1(86.564,17.889)
MCU_P0.1: J101.25 R6.2 U1.32 | length 55.1
  Top Layer w0.1: v1(83.05,38.25) R6.2@83.05,37.6 83.25,37.8 84.85,37.8 U1.32@84.85,37.45
  Signal Layer 3 w0.1: J101.25@61.43,3.262 62.75,4.582 62.75,6.3 64.231,7.781 67.781,7.781 79.25,19.25 v1@85.475,19.25
  Signal Layer 4 w0.1: v1(83.05,38.25) 83.05,37.45 86.1,34.4 86.1,32.6 85.825,32.325 85.825,19.625 v1(85.475,19.275)
MCU_P0.2: C102.1 J101.23 R100.1 SW100.3 SW100.4 TPJ652.1 U1.31 U950.8 | length 114.7
  Top Layer w0.1: C102.1@50.45,11.725 50.975,11.725 R100.1@51,11.7 51.225,11.925 SW100.3@51.925,11.925 SW100.4@56.075,11.925 v1(57.075,11.925) ; v1(51.9,44.088) 52.353,44.088 U950.8@52.425,44.015 ; U1.31@85.35,37.45 v1(85.35,38.225)
  Signal Layer 3 w0.1: J101.23@58.89,3.262 60.2,4.572 60.2,6.2 63,9 67.8,9 79,20.2 86.2,20.2 v1(87,19.4)
  Signal Layer 4 w0.1: v1(51.9,44.088) 52.787,44.088 54.4,42.475 54.4,37.5 57.075,34.825 v1(57.075,11.925) ; v1(85.35,38.225) 85.35,37.125 87.025,35.45 87.025,32.625 86.35,31.95 86.35,31.125 86.5,30.975 86.5,19.9 v1(87,19.4)
  Bottom Layer w0.1: v1(57.075,11.925) v1@57.1,11.9 ; J101.23@58.89,3.262 57.5,4.652 57.5,11.5 v1@57.1,11.9 ; TPJ652.1@61.303,16.102 v1@57.1,11.9
MCU_P0.3: C103.1 J101.21 R101.1 SW101.3 SW101.4 TPJ653.1 U1.30 U950.11 | length 126.1
  Top Layer w0.1: C103.1@38.45,11.725 38.975,11.725 R101.1@39,11.7 39.225,11.925 SW101.3@39.925,11.925 SW101.4@44.075,11.925 v1(45.075,11.925) ; U950.11@53.625,44.015 53.625,43.725 53.8,43.55 53.85,43.55 53.875,43.525 53.9,43.525 53.908,43.525 54.029,43.404 54.271,43.404 54.4,43.275 54.4,43.05 54.825,42.625 v1(54.825,42.575) ; v1(85.375,39.025) 85.85,38.55 U1.30@85.85,37.45
  Signal Layer 3 w0.1: v1(45.075,11.925) 46.875,11.925 v1(51.05,16.1) v1(57.6,16.1) ; J101.21@56.35,3.262 57.8,4.712 57.8,6.4 61.5,10.1 67.7,10.1 78.6,21 v1(87.6,21)
  Signal Layer 4 w0.1: v1(54.825,42.575) 54.6,42.35 54.6,37.65 57.6,34.65 v1(57.6,16.1) 57.6,4.512 J101.21@56.35,3.262 ; v1(85.375,39.025) 85.85,38.55 85.85,37.025 87.275,35.6 87.275,32.475 86.575,31.775 86.575,31.225 86.825,30.975 86.825,21.775 v1(87.6,21)
  Bottom Layer w0.1: v1(51.05,16.1) 51.052,16.102 TPJ653.1@51.953,16.102
MCU_P0.4: J101.19 U1.29 U812.2 | length 82.2
  Top Layer w0.1: v1(66.65,28.5) 66.625,28.5 66.7,28.575 U812.2@66.7,29.165 ; U1.29@86.35,37.45 v1(86.35,38.225)
  Signal Layer 3 w0.1: J101.19@53.81,3.262 55.05,4.502 55.05,6.325 56.2,7.475 57.175,7.475 60.9,11.2 67.6,11.2 78.85,22.45 v1@87.225,22.45 ; v1(66.65,28.5) 66.65,27.825 66.95,27.525 68,27.525 68.5,27.025 74.625,27.025 75.25,27.65 v1(87.3,27.65)
  Signal Layer 4 w0.1: v1(86.35,38.225) 86.35,37 87.5,35.85 87.5,31.225 87.3,31.025 v1(87.3,27.65) 87.3,22.525 v1@87.225,22.45
  other v1: 87.3,22.45
MCU_P0.5: J101.17 U1.28 U812.4 | length 87.3
  Top Layer w0.1: U812.4@67.5,29.165 67.5,28.5 v1(68,28) ; U1.28@86.85,37.45 v1@86.85,38.85
  Signal Layer 3 w0.1: J101.17@51.27,3.262 52.55,4.542 52.55,6.35 54.8,8.6 57,8.6 62.775,14.375 68.375,14.375 77.45,23.45 87.675,23.45 v1(88.275,22.85) ; v1(68,28) 69.275,28 69.975,27.3 74.3,27.3 75.6,28.6 84.375,28.6 84.8,28.175 v1(87.75,28.175)
  Signal Layer 4 w0.1: v1(86.85,38.875) 86.85,37.925 88.3,36.475 88.3,33.45 87.75,32.9 v1(87.75,28.175) 87.75,23.375 v1(88.275,22.85)
MCU_P1.4: J101.20 R135.2 U1.21 | length 65.2
  Top Layer w0.1: R135.2@69.8,13.55 v1(69.8,14.2) ; U1.21@89.05,35.25 v1(90.325,35.25)
  Signal Layer 3 w0.1: J101.20@53.81,5.802 53.81,6.06 55.85,8.1 57.2,8.1 60.9,11.8 67.4,11.8 v1(69.8,14.2) 78.55,22.95 87.45,22.95 88.125,22.275 93.775,22.275 v1(94.1,22.6)
  Signal Layer 4 w0.1: v1(90.325,35.25) 91.475,35.25 94.6,32.125 94.6,23.1 v1(94.1,22.6)
MCU_P1.5: J101.18 R136.2 U1.20 | length 66.1
  Top Layer w0.1: R136.2@68.95,15.15 v1(68.95,15.8) ; U1.20@89.05,34.75 v1@90.95,34.75
  Signal Layer 3 w0.1: J101.18@51.27,5.802 54.759,9.291 57.091,9.291 62.6,14.8 68.075,14.8 68.95,15.675 v1(68.95,15.8) 77.1,23.95 87.875,23.95 89.075,22.75 92.3,22.75 v1(93.75,24.2)
  Signal Layer 4 w0.1: v1(90.975,34.75) 91.45,34.75 94.2,32 94.2,24.65 v1(93.75,24.2)
MCU_P1.6: J101.16 R137.2 U1.19 | length 66.5
  Top Layer w0.1: R137.2@68.05,15.15 v1(68.05,15.8) ; U1.19@89.05,34.25 v1(90.325,34.25)
  Signal Layer 3 w0.1: J101.16@48.73,5.802 53.428,10.5 57,10.5 62.3,15.8 v1(68.05,15.8) 68.05,16.35 76.7,25 88.1,25 88.8,24.3 92.175,24.3 v1(93.75,25.875)
  Signal Layer 4 w0.1: v1(90.325,34.25) 91.275,34.25 93.75,31.775 v1(93.75,25.875)
MCU_P1.7: C106.1 J101.14 R111.1 SW105.5 U1.18 | length 77.9
  Top Layer w0.1: v1(82.8,13.525) 83.212,13.113 84.522,11.802 SW105.5@84.522,11.528 ; U1.18@89.05,33.75 v1@90.95,33.75
  Signal Layer 3 w0.1: J101.14@46.19,5.802 45,4.612 45,2.55 45.7,1.85 70.375,1.85 82.05,13.525 v1(82.8,13.525)
  Signal Layer 4 w0.1: v1(82.8,13.525) 86.15,16.875 89.55,16.875 91.775,19.1 91.775,26.675 91.15,27.3 91.15,32.15 91.6,32.6 91.6,33.125 v1(90.975,33.75)
MCU_P2.2: J102.23 R841.1 U1.15 | length 92.1
  Top Layer w0.1: v1(61.85,28.225) R841.1@62.4,28.225 ; U1.15@87.85,32.55 87.85,32.275 88.6,31.525 88.6,31.375 89,30.975 89.325,30.975 v1(89.75,30.55)
  Signal Layer 3 w0.1: J102.23@58.89,54.062 60.153,55.325 70.775,55.325 71.8,54.3 85.55,54.3 v1(86.25,55) ; v1(61.85,28.225) 62.875,27.2 67.825,27.2 69.025,26 74.4,26 75.1,26.7 v1(90.2,26.7)
  Signal Layer 4 w0.1: v1(86.25,55) 86.2,54.95 86.2,51.45 88.95,48.7 88.95,39.025 88.375,38.45 88.375,37.75 89.175,36.95 89.175,32.9 89.75,32.325 v1(89.75,30.55) 89.75,27.15 v1(90.2,26.7)
MCU_P2.5: J102.17 R305.1 | length 54.2
  Top Layer w0.1: v1(84.525,30.775) 84.525,30.825 85,31.3 R305.1@85.45,31.3
  Signal Layer 3 w0.1: J102.17@51.27,54.062 52.307,53.025 55.175,53.025 55.8,52.4 62.6,52.4 64.1,50.9 64.8,50.9 65.55,51.65 v1(78.75,51.65)
  Signal Layer 4 w0.1: v1(78.75,51.65) 79.075,51.325 79.075,51.05 82.3,47.825 82.3,37.475 84.775,35 84.775,33.55 85.3,33.025 85.3,31.55 v1(84.525,30.775)
MCU_P2.6: J102.15 R300.1 U1.11 | length 57.4
  Top Layer w0.1: R300.1@62.5,50.55 v1(62.5,51.6) ; v1(84.25,31.425) 84.6,31.775 85.4,31.775 85.85,32.225 U1.11@85.85,32.55
  Signal Layer 3 w0.1: J102.15@48.73,54.062 49.992,52.8 55.075,52.8 55.75,52.125 61.975,52.125 v1(62.5,51.6) 63.5,50.6 65,50.6 65.625,51.225 v1(78.3,51.225)
  Signal Layer 4 w0.1: v1(78.3,51.225) 82,47.525 82,37.4 84.45,34.95 84.45,33.4 84.9,32.95 84.9,32.075 v1(84.25,31.425)
MCU_P3.4: J102.20 R304.1 U1.6 | length 49.9
  Top Layer w0.1: R304.1@64.5,50.55 v1(64.5,51.6) ; v1(82.225,33.15) 82.725,33.15 83.825,34.25 U1.6@84.15,34.25
  Signal Layer 3 w0.1: J102.20@53.81,56.602 55.1,55.312 55.1,53.775 55.875,53 63.1,53 v1(64.5,51.6) 65.325,52.425 v1(74.475,52.425)
  Signal Layer 4 w0.1: v1(74.475,52.425) 74.475,48.325 79.219,43.581 79.219,38.131 81.9,35.45 81.9,34.2 82.225,33.875 v1(82.225,33.15)
MCU_P3.7: J102.18 R303.1 | length 6.2
  Top Layer w0.1: R303.1@48.65,51.5 50,52.85 50,55.332 J102.18@51.27,56.602
N16809528: D703.1 P700.1 Q703.3 ST701.2 | length 60.2
  Top Layer w0.5: ST701.2@2.875,4.62 3.82,4.62 v1@4.087,4.887 ; v1(4.087,4.981) v1@4.087,4.887 ; P700.1@7,6.078 5.278,6.078 v1@4.087,4.887 ; v1(10.046,4.981) 12.019,4.981 12.675,4.325 D703.1@13.2,4.325 14.525,4.325 14.8,4.6 Q703.3@14.8,5.325
  Top Layer w1: P700.1@5.947,5.025 P700.1@7,6.078
  Signal Layer 4 w0.6: v1(3.958,7.181) 3.958,4.988 3.962,4.984 3.962,4.981 v1(4.087,4.981) v1(10.046,4.981) v1(10.046,6.081) v1(10.046,7.181) 11.714,7.181 17.039,12.506 17.039,20.919 11.133,26.825 v1(10.046,26.825) v1(10.046,27.925) 10.046,29.025 v1(3.958,29.025) 3.958,29.023 3.962,29.019 v1(3.962,27.925) v1(3.962,26.825)
  other v1: 3.962,6.081
N16809565: Q703.2 SW704.6 TP156.1 | length 5.4
  Top Layer w0.5: Q703.2@15.3,3.65 Q703.2@15.325,3.625
  Top Layer w0.635: Q703.2@15.325,3.625 v1(15.8,3.625) 17.15,3.625 18.4,2.375 SW704.6@18.4,1.75
  Bottom Layer w0.3: TP156.1@15.3,4.6 15.8,4.1 v1(15.8,3.625)
N16809744: R793.1 SW704.1 | length 2.1
  Top Layer w0.1: SW704.1@23.4,7.25 23.4,8 R793.1@24.7,8
N16809746: R794.1 SW704.3 | length 2
  Top Layer w0.1: R794.1@17.1,7.95 18.4,7.95 SW704.3@18.4,7.25
N16812963: Q703.1 R792.2 | length 0.8
  Top Layer w0.1: R792.2@14.275,2.9 14.3,2.925 Q703.1@14.3,3.65
N16831167: R700.1 U701.7 | length 0.9
  Top Layer w0.1: U701.7@31.35,30.35 31.35,29.525 R700.1@31.425,29.45
N16831188: C705.1 U701.6 | length 0.9
  Top Layer w0.1: U701.6@30.85,30.35 30.85,29.45 C705.1@30.875,29.425
N16831199: R702.1 R703.2 U701.5 | length 1.5
  Top Layer w0.1: R703.2@29.775,29.45 R702.1@30.325,29.45 30.35,29.475 U701.5@30.35,30.35
N16831281: R705.2 TP711.1 U702.11 | length 3.4
  Top Layer w0.1: v1(39.75,35.875) 40.075,35.875 R705.2@40.4,36.2 40.475,36.275 U702.11@41.815,36.275
  Bottom Layer w0.1: TP711.1@39.7,34.7 39.75,34.75 v1(39.75,35.875)
N16831285: R706.2 TP712.1 U702.8 | length 2.7
  Top Layer w0.1: v1(40.5,38) R706.2@41,37.5 41.025,37.475 U702.8@41.815,37.475
  Bottom Layer w0.1: TP712.1@39.7,38.8 v1(40.5,38)
N16831289: R707.2 TP713.1 U702.3 | length 2.7
  Top Layer w0.1: U702.3@43.585,36.675 44.225,36.675 R707.2@44.4,36.5 44.5,36.6 44.9,36.6 v1(44.95,36.65)
  Bottom Layer w0.1: TP713.1@43.8,36.7 43.85,36.65 v1(44.95,36.65)
N16831309: R708.2 TP714.1 U702.1 | length 2.8
  Top Layer w0.1: v1(43.625,35.475) 43.625,35.5 43.585,35.54 U702.1@43.585,35.875 44.3,35.875 R708.2@44.4,35.775
  Bottom Layer w0.1: TP714.1@43.2,34.1 43.2,35.05 v1(43.625,35.475)
N16831821: C707.1 L702.2 U702.14 | length 1.9
  Top Layer w0.2: C707.1@42.85,34.975 42.9,35.025 U702.14@42.9,35.79
  Top Layer w0.3: L702.2@42.435,34.05 42.85,34.465 C707.1@42.85,34.975
N16835747: Q705.3 Q705.6 Q705.7 Q705.8 U700.3 | length 4.1
  Top Layer w0.6: U700.3@24.8,34.075 25.038,34.313 Q705.6@25.9,34.313 25.9,33.583 Q705.7@26.084,33.4 Q705.8@27.017,33.4 27.2,33.217 Q705.3@27.2,32.488
N16839091: R709.1 U703.1 U703.2 | length 3.3
  Top Layer w0.1: U703.2@30.25,39.65 30.825,39.65 30.95,39.525 30.95,39.325 30.775,39.15 U703.1@30.25,39.15 30.25,37.7 R709.1@30.35,37.6
N16839103: C710.2 U703.6 | length 0.8
  Top Layer w0.25: C710.2@26.65,40.175 26.675,40.15 U703.6@27.45,40.15
N16839111: C729.1 R718.2 U703.4 U704.3 U704.5 | length 9.5
  Top Layer w0.1: U704.3@25.545,44.275 27,44.275 27.65,43.625 U704.5@29.6,43.625 ; U704.5@29.756,43.625 U704.5@29.6,43.625 ; U703.4@30.225,40.675 U703.4@30.25,40.65 ; R718.2@31.925,40.925 31.3,40.925 C729.1@31.025,40.65 U703.4@30.25,40.65 ; U704.5@29.6,43.625 29.6,42 30.25,41.35 U703.4@30.25,40.65
N16839131: R710.1 U703.8 | length 2.6
  Top Layer w0.1: U703.8@27.45,39.15 27.45,38.775 27.775,38.45 28.3,38.45 R710.1@29.15,37.6
N16839143: L700.2 R717.1 | length 1
  Top Layer w0.5: L700.2@24.65,37.5 R717.1@25.6,37.5
N16839420: C766.1 R765.1 R767.2 U704.2 | length 3.1
  Top Layer w0.1: R767.2@23.8,43.15 R765.1@23.8,44.2 24.225,44.625 C766.1@24.7,44.625 25,44.925 U704.2@25.545,44.925
N16839426: C766.2 R764.1 R765.2 U704.1 | length 3.6
  Top Layer w0.1: R764.1@23.725,46.875 23.725,45.675 R765.2@23.8,45.6 24.225,45.175 C766.2@24.7,45.175 24.7,45.5 24.775,45.575 U704.1@25.545,45.575
N16839472: C770.1 R769.1 R771.2 U704.6 | length 3.5
  Top Layer w0.1: U704.6@29.756,44.275 30.475,44.275 C770.1@30.6,44.4 30.9,44.1 31.1,44.1 R769.1@31.5,43.7 31.2,43.4 31.2,43 R771.2@30.8,42.6
N16839478: C770.2 R768.1 R769.2 U704.7 | length 2.7
  Top Layer w0.1: U704.7@29.756,44.925 29.781,44.95 C770.2@30.6,44.95 R769.2@31.35,44.95 ; R769.2@31.5,45.1 R768.1@31.5,46.2
N16839586: C730.1 C731.1 R731.1 U704.8 | length 3.8
  Top Layer w0.5: R731.1@28.25,48.5 28.725,48.5 29.7,47.525 C731.1@29.7,47.4 29.755,47.345 29.755,45.631 U704.8@29.7,45.631
N16839602: L704.2 R731.2 | length 0.9
  Top Layer w0.5: L704.2@27.275,49.4 27.275,48.575 R731.2@27.35,48.5
N16846192: R808.2 U802.6 U802.12 U803.C1 U806.5 U806.6 U806.12 U806.13 | length 30.1
  Top Layer w0.1: v1(60.325,35.013) 60.638,35.325 U803.C1@60.9,35.325 ; U806.6@69.9,35.8 69.9,36.275 69.975,36.35 70.25,36.35 ; U802.6@69.9,40.3 69.912,40.312 69.912,40.912 v1(69.975,40.975) ; U806.5@70.4,35.8 70.4,36.2 70.25,36.35 ; v1@71.4,32.7 U806.12@71.4,33.4 ; U802.12@71.4,37.9 71.4,37.275 v1(71.275,37.15) 70.669,37.15 70.25,36.731 70.25,36.35 ; v1(71.5,32.625) R808.2@72.025,32.625 72.025,33 71.9,33.125 U806.13@71.9,33.4
  Signal Layer 3 w0.1: v1(60.325,35.013) 60.325,34.375 61.075,33.625 68.925,33.625 69.075,33.475 70.65,33.475 v1(71.5,32.625)
  Signal Layer 4 w0.1: v1(69.975,40.975) 71.275,39.675 v1(71.275,37.15) 70.6,37.15 70.25,36.8 70.25,35.7 71.5,34.45 v1(71.5,32.625)
N16846231: C804.1 C810.1 L801.2 U804.A2 U809.A2 | length 9.7
  Top Layer w0.2: U804.A2@51.325,37.4 51.325,37.15 51.825,36.65 C804.1@51.9,36.65 53.6,36.65 v1(53.65,36.7) ; v1(51.5,40.3) C810.1@52.025,40.3 52.05,40.325 U809.A2@52.05,40.925
  Top Layer w0.3: v1(53.65,36.7) L801.2@53.65,37.3
  Signal Layer 4 w0.25: 51.5,39.8 51.55,39.75 51.55,39.375 51.6,39.325
  Signal Layer 4 w0.3: 51.5,39.8 v1(51.5,40.3) ; 51.6,39.325 51.9,39.025 51.9,37.325 52.525,36.7 v1(53.65,36.7)
N16846319: Q800.1 U806.10 | length 9.8
  Top Layer w0.1: Q800.1@68.325,37.95 v1@68.325,38.625 ; v1(69.15,32.175) 69.425,32.175 70.4,33.15 U806.10@70.4,33.4
  Signal Layer 4 w0.1: v1@68.375,38.625 67.925,38.175 67.925,33.206 68.956,32.175 v1(69.15,32.175)
  other v1: 68.35,38.625
N16846537: RP801.5 U808.21 | length 1.1
  Top Layer w0.1: U808.21@65.195,44.3 RP801.5@66.25,44.3
N16846539: RP801.6 U808.20 | length 1.1
  Top Layer w0.1: U808.20@65.195,43.8 RP801.6@66.25,43.8
N16846547: RP801.7 U808.19 | length 1.1
  Top Layer w0.1: U808.19@65.195,43.3 RP801.7@66.25,43.3
N16846551: RP801.8 U808.18 | length 1.1
  Top Layer w0.1: U808.18@65.195,42.8 RP801.8@66.25,42.8
N16846567: Q800.2 R815.1 | length 1.8
  Top Layer w0.1: R815.1@66.6,38.05 66.6,38 67.15,37.45 67.5,37.45 67.825,37.775 Q800.2@67.825,37.95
